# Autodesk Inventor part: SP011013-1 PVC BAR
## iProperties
Created: 2013-01
Part Number: SP011013-1 PVC BAR
Material: PVC-U
Document SubType Name: Modeling
Designer: Administrator
Density: 1.4 g/cm^3
Mass: 54.0443 g
Surface Area: 243.802 cm^2
Volume: 38.6031 cm^3
Author: Administrator
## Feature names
1. Extrusion1
